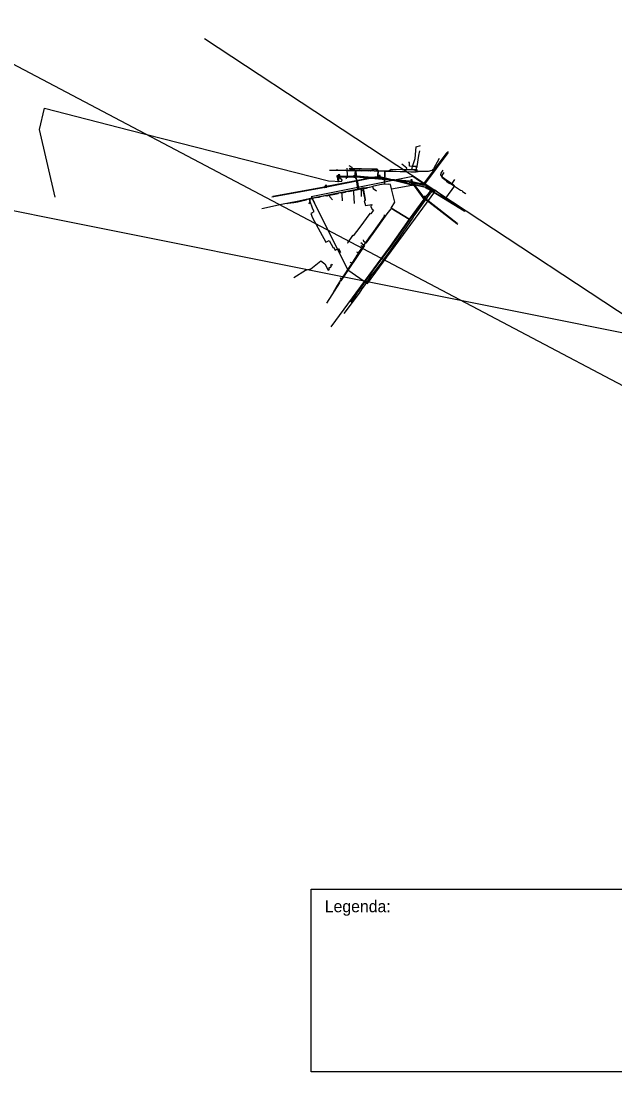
# Model space of a CAD drawing. Extents: x -748299 to -739481, y -1044416 to -1042142.
# Drawn here: x -742397 to -741644, y -1044416 to -1043083 of the extents above; entities that cross this region are included whole.
import ezdxf

# ---------------------------------------------------------------- set-up
doc = ezdxf.new("R2010")
doc.units = 0
for name, color, linetype in [('Vrstva 1', 7, 'Continuous'), ('Vrstva 2', 7, 'Continuous'), ('Vrstva 3', 7, 'Continuous'), ('Vrstva 5', 7, 'Continuous'), ('Vrstva 63', 7, 'Continuous')]:
    doc.layers.add(name, color=color, linetype=linetype)

msp = doc.modelspace()

# ---------------------------------------------------------------- linework, layer by layer
at = {"layer": 'Vrstva 1'}
for points in [[(-741897, -1043257.6), (-741895.6, -1043243), (-741890.1, -1043241)], [(-742005.4, -1043272.4), (-741996.1, -1043272.5), (-741983.4, -1043272.8)], [(-741997.2, -1043272.1), (-741994.8, -1043272.2), (-741991.4, -1043272.3), (-741985.3, -1043272.4), (-741984.3, -1043272), (-741983.3, -1043272.4), (-741978.9, -1043272.5)], [(-741983.4, -1043272.8), (-741975, -1043273), (-741964.6, -1043273.2), (-741951.8, -1043273)], [(-741980.6, -1043270), (-741978.3, -1043271.6)], [(-741978.9, -1043272.5), (-741977.2, -1043272.5)], [(-741978.3, -1043270.1), (-741967.9, -1043270.3), (-741965.1, -1043270.4), (-741946, -1043270.8), (-741945.6, -1043271.3)], [(-741978.3, -1043271.6), (-741973.5, -1043271.7), (-741971.5, -1043272), (-741968, -1043272.2), (-741967.1, -1043272.5), (-741955.2, -1043272.5), (-741945.6, -1043271.3)], [(-741977.2, -1043272.5), (-741972.7, -1043272.4)], [(-741973.2, -1043280.5), (-741973, -1043277.5), (-741972.7, -1043272.4)], [(-741972.7, -1043272.4), (-741973, -1043277.5), (-741973.2, -1043280.5), (-741971.9, -1043283.2), (-741970.8, -1043285.7)], [(-741972.7, -1043272.4), (-741971.7, -1043272.4), (-741967.7, -1043272.7), (-741960.5, -1043272.9), (-741956.3, -1043273.2), (-741954.9, -1043272.6), (-741953.4, -1043273.1), (-741946.8, -1043272.9), (-741945.2, -1043272.6), (-741943.5, -1043273.1), (-741934.5, -1043273.2), (-741929.4, -1043272.9), (-741921.1, -1043273.7), (-741909.8, -1043274), (-741908.9, -1043273.2), (-741907.3, -1043269.8), (-741913.8, -1043264.8)], [(-741967.7, -1043272.7), (-741971.7, -1043272.4)], [(-741967.9, -1043270.3), (-741965.1, -1043270.4)], [(-741951.8, -1043273), (-741948.8, -1043273.1)], [(-741948.8, -1043273.1), (-741944, -1043273.4)], [(-741945.6, -1043271.3), (-741944.6, -1043271.2)], [(-741945.6, -1043271.3), (-741944, -1043273.1)], [(-741944, -1043273.1), (-741944.6, -1043271.2)], [(-741944, -1043273.4), (-741944.1, -1043279.7), (-741944.3, -1043280.2)], [(-741944.1, -1043279.7), (-741944, -1043273.4)], [(-741944, -1043273.1), (-741944, -1043273.4)], [(-741944, -1043273.1), (-741943.7, -1043273.4)], [(-741944, -1043273.4), (-741943.7, -1043273.4)], [(-741943.7, -1043273.4), (-741935.2, -1043273.6)], [(-741935.2, -1043273.6), (-741935.8, -1043289.8)], [(-741935.2, -1043273.6), (-741931, -1043273.7)], [(-741931, -1043273.7), (-741927.2, -1043271.2), (-741913.2, -1043271.5), (-741906.2, -1043271.6), (-741901.3, -1043271.7)], [(-741931, -1043273.7), (-741916.1, -1043274), (-741902.2, -1043274.5), (-741898.2, -1043274.6), (-741895, -1043274.6), (-741895.1, -1043273.9)], [(-741902.2, -1043274.5), (-741898.2, -1043274.6)], [(-741895.2, -1043271.7), (-741895.1, -1043271)], [(-741895.2, -1043273), (-741895.2, -1043271.7)], [(-741895.1, -1043273.9), (-741895.2, -1043273)], [(-741895.1, -1043270.6), (-741895.1, -1043270)], [(-741895.1, -1043271), (-741895.1, -1043270.6)], [(-741861.7, -1043272.3), (-741864.2, -1043276.3), (-741864.6, -1043278.2), (-741862.6, -1043281.9), (-741857.6, -1043285.6), (-741857.2, -1043286.4), (-741854.5, -1043288.3), (-741853, -1043289.4), (-741850.7, -1043290)], [(-741970.8, -1043285.7), (-741971.9, -1043283.2), (-741973.2, -1043280.5)], [(-741970.8, -1043285.7), (-741971.1, -1043287.2), (-741969.8, -1043296.3), (-741969.1, -1043296.8)], [(-741970.8, -1043285.7), (-741971.1, -1043287.2)], [(-741971.1, -1043287.2), (-741969.8, -1043296.3)], [(-741970.8, -1043285.7), (-741970.6, -1043287.2), (-741969.2, -1043296.1), (-741969.1, -1043296.8)], [(-741970.8, -1043285.7), (-741970.2, -1043287.1), (-741968.7, -1043295.9), (-741969.1, -1043296.8)], [(-741970.8, -1043285.7), (-741970.6, -1043287.2)], [(-741970.2, -1043287.1), (-741970.8, -1043285.7)], [(-741970.6, -1043287.2), (-741969.2, -1043296.1)], [(-741968.7, -1043295.9), (-741970.2, -1043287.1)], [(-741859.8, -1043283), (-741849.6, -1043289.7)], [(-741857.6, -1043285.6), (-741857.2, -1043286.4), (-741854.5, -1043288.3)], [(-741846.9, -1043284.3), (-741848.8, -1043286.9), (-741850.7, -1043290)], [(-741848.8, -1043286.9), (-741850.7, -1043290)], [(-742031.1, -1043308.4), (-742011.4, -1043304.6), (-742001, -1043302.6), (-741979.3, -1043298.2), (-741965.1, -1043295.3)], [(-742005.8, -1043304.2), (-742000.7, -1043303.3), (-741994.6, -1043302.1), (-741993.6, -1043301.2), (-741991.3, -1043300.8), (-741989.8, -1043301)], [(-741989.8, -1043301), (-741985.7, -1043300.2), (-741983.2, -1043299.1), (-741981.3, -1043299.3), (-741969.1, -1043296.8)], [(-741985.7, -1043300.2), (-741989.8, -1043301)], [(-741989, -1043311.3), (-741989.4, -1043303.2), (-741989.8, -1043301)], [(-741969.1, -1043296.8), (-741965.6, -1043296.2)], [(-741965.6, -1043296.2), (-741964.7, -1043295.9), (-741961.1, -1043295.2), (-741958.8, -1043295.2), (-741956.7, -1043294.3), (-741951, -1043293.2), (-741950.3, -1043295.5)], [(-741965.6, -1043296.2), (-741965.1, -1043298.7)], [(-741961.1, -1043295.2), (-741964.7, -1043295.9)], [(-741961.8, -1043294.9), (-741955.4, -1043293.8)], [(-741955.4, -1043293.8), (-741951.4, -1043293)], [(-741951.4, -1043293), (-741949.1, -1043292.5)], [(-741950.3, -1043295.5), (-741946, -1043298.7)], [(-741949.1, -1043292.5), (-741939.7, -1043290.4)], [(-741939.7, -1043290.4), (-741938.9, -1043290.2)], [(-741927, -1043296.1), (-741928.3, -1043290.7), (-741930.6, -1043290.4)], [(-741927, -1043296.1), (-741901, -1043291.5), (-741899, -1043291.2)], [(-741927, -1043296.1), (-741901, -1043291.5)], [(-741878.3, -1043299.5), (-741881.5, -1043304)], [(-741875.9, -1043298.7), (-741878.3, -1043299.5)], [(-741847.1, -1043292.4), (-741858.4, -1043307.9)], [(-741850.7, -1043290), (-741839.5, -1043298), (-741837.8, -1043298.1), (-741837.2, -1043298.5), (-741836.8, -1043299.6), (-741833.5, -1043301.8), (-741832.6, -1043302.5)], [(-741849.6, -1043289.7), (-741847.1, -1043292.4)], [(-742091.1, -1043321.1), (-742066.5, -1043315.7), (-742046.3, -1043311.8), (-742031.1, -1043308.4)], [(-742059.2, -1043314.6), (-742057.9, -1043314.3), (-742054.5, -1043313.9), (-742050.7, -1043313.5), (-742045.5, -1043312.4), (-742042.1, -1043311.6), (-742034.9, -1043310.1), (-742033.4, -1043309.4), (-742030.4, -1043309)], [(-742045.5, -1043312.4), (-742042.1, -1043311.6)], [(-742030.4, -1043309), (-742029.2, -1043308.8), (-742028.8, -1043308.8)], [(-742028.8, -1043308.8), (-742027.2, -1043308.4)], [(-742016.6, -1043306.3), (-742018.2, -1043306.6), (-742021.5, -1043307.2), (-742027.2, -1043308.4)], [(-742027.2, -1043308.4), (-742026.7, -1043310.5)], [(-742026.7, -1043310.5), (-742024.6, -1043313.7)], [(-742021.5, -1043307.2), (-742018.2, -1043306.6)], [(-742005.8, -1043304.2), (-742008.7, -1043305.4), (-742010.9, -1043305.2), (-742016.6, -1043306.3)], [(-742001.5, -1043310.2), (-742005.2, -1043306.4), (-742005.8, -1043304.2)], [(-741841.5, -1043319.7), (-741865.5, -1043305.2)], [(-741936.8, -1043329.1), (-741935.4, -1043330.1)], [(-741927.3, -1043320.8), (-741904.3, -1043334.4)], [(-741899.3, -1043332.2), (-741897, -1043328.7)], [(-741935.4, -1043330.1), (-741951.7, -1043353.1), (-741953.5, -1043355.5), (-741963.6, -1043369.7)], [(-741899.3, -1043332.2), (-741908.8, -1043345.5), (-741926.1, -1043370.6), (-741933.2, -1043380.7)], [(-741951.7, -1043353.1), (-741953.5, -1043355.5)], [(-741964, -1043366), (-741961.2, -1043368), (-741991.2, -1043412.9), (-741992.7, -1043413.8), (-741992.8, -1043415.5), (-742009.3, -1043441.2)], [(-741927.8, -1043369.4), (-741949.6, -1043398.5), (-741971.4, -1043429.2), (-741973.5, -1043432.5)], [(-741963.6, -1043369.7), (-741965.6, -1043368.3)], [(-741970.2, -1043379.4), (-741970.8, -1043380.3), (-741972.6, -1043383.1), (-741977.3, -1043390.3)], [(-741970.8, -1043380.3), (-741972.6, -1043383.1)], [(-741969, -1043377.4), (-741970.8, -1043376.3)], [(-741969, -1043377.4), (-741970.2, -1043379.4)], [(-741963.6, -1043369.7), (-741969, -1043377.4)], [(-741933.2, -1043380.7), (-741936, -1043384.4)], [(-741977.3, -1043390.3), (-741990.1, -1043410.1)], [(-741977.3, -1043390.3), (-741978.9, -1043389.4)], [(-741938.8, -1043388.1), (-741947.7, -1043399.8), (-741951.4, -1043404.2)], [(-741936, -1043384.4), (-741938.8, -1043388.1)], [(-741991.4, -1043409.3), (-741990.1, -1043410.1)], [(-741953.2, -1043406.5), (-741956.8, -1043412.6)], [(-741951.4, -1043404.2), (-741953.2, -1043406.5)], [(-741990.6, -1043410.8), (-741995.7, -1043418.7), (-741997.4, -1043421.6), (-742000.5, -1043426.7)], [(-741995.7, -1043418.7), (-741997.4, -1043421.6)], [(-741990.1, -1043410.1), (-741990.6, -1043410.8)], [(-741961.7, -1043419.2), (-741964.4, -1043422.8)], [(-741960.8, -1043417.9), (-741961.7, -1043419.2)], [(-741958.2, -1043414.5), (-741960.8, -1043417.9)], [(-741956.8, -1043412.6), (-741958.2, -1043414.5)], [(-741967.9, -1043428.5), (-741987.2, -1043454.2)], [(-741973.5, -1043432.5), (-741978.9, -1043439.7)], [(-741964.4, -1043422.8), (-741967.9, -1043428.5)]]:
    msp.add_lwpolyline(points, dxfattribs=at)
msp.add_lwpolyline([(-742028.7, -1044184.3), (-740808.7, -1044184.3), (-740808.7, -1044416.3), (-742028.7, -1044416.3)], close=True, dxfattribs=at)
at = {"layer": 'Vrstva 2'}
for points in [[(-742353.5, -1043306.5), (-742373, -1043220.8), (-742367, -1043194), (-742258.5, -1043221.6), (-742006.7, -1043285.8), (-741990.4, -1043286.8), (-741989.5, -1043284.6), (-741992.7, -1043282.5), (-741994.5, -1043282.4), (-741994.5, -1043280.3)], [(-741855.1, -1043248.9), (-741885.4, -1043290), (-741886.5, -1043291.1), (-741902.5, -1043286.9), (-741973.2, -1043280.5)], [(-741895.1, -1043270), (-741894.3, -1043267.8), (-741892.3, -1043253.9), (-741891, -1043248.1)], [(-741900.1, -1043267.6), (-741904.1, -1043267.4), (-741904.1, -1043262.7), (-741905.3, -1043262.7)], [(-741900.1, -1043267.6), (-741897, -1043257.6)], [(-741866.5, -1043257.5), (-741873.7, -1043270.7), (-741875.8, -1043272.7), (-741880.2, -1043274.1), (-741893, -1043274.2)], [(-741983.4, -1043272.8), (-741982.8, -1043281.7), (-741984.7, -1043282.5), (-741984.3, -1043283.4)], [(-741983.6, -1043270), (-741983.4, -1043272.8)], [(-741981, -1043266.6), (-741977.2, -1043268.5), (-741977.2, -1043272.5)], [(-741978.3, -1043271.6), (-741978.3, -1043270.1)], [(-741935.8, -1043289.8), (-741935.2, -1043273.6)], [(-741901.3, -1043271.7), (-741900.1, -1043267.6)], [(-741901.3, -1043271.7), (-741899.7, -1043271.7)], [(-741895.1, -1043270), (-741895.8, -1043267.8), (-741900.1, -1043267.6)], [(-741899.7, -1043271.7), (-741895.2, -1043271.7)], [(-741895.1, -1043273.9), (-741899.7, -1043271.7)], [(-741895.2, -1043271.7), (-741894.6, -1043271.7), (-741894.3, -1043274.2)], [(-741895.1, -1043273.9), (-741894.3, -1043274.2)], [(-741894.3, -1043274.2), (-741893, -1043274.2)], [(-741860.5, -1043275.5), (-741863.1, -1043279.1), (-741862.8, -1043280.8), (-741859.8, -1043283)], [(-742078.7, -1043306.3), (-742010.8, -1043293.8), (-741945.3, -1043281), (-741943.3, -1043281.1)], [(-741973.2, -1043280.5), (-741994.5, -1043280.3)], [(-741944.3, -1043280.2), (-741943.3, -1043281.1)], [(-741943.3, -1043281.1), (-741941.7, -1043281), (-741900.5, -1043291.1), (-741899, -1043291.2)], [(-741974, -1043314.7), (-741974.5, -1043300.6), (-741975, -1043297.8), (-741963.5, -1043295.9), (-741960.6, -1043309.6), (-741960.4, -1043311)], [(-741964.8, -1043305.9), (-741965.1, -1043298.7), (-741965.6, -1043296.2)], [(-741963, -1043295.1), (-741965.1, -1043295.3)], [(-741961.8, -1043294.9), (-741963, -1043295.1)], [(-741963, -1043295.1), (-741960.2, -1043309.6), (-741960.4, -1043311)], [(-741938.9, -1043290.2), (-741935.8, -1043289.8)], [(-741935.8, -1043289.8), (-741930.6, -1043290.4)], [(-741904.3, -1043334.4), (-741927.3, -1043320.8), (-741922.7, -1043313), (-741927, -1043296.1)], [(-741899, -1043291.2), (-741897.9, -1043291.9), (-741886.6, -1043307), (-741885.6, -1043307.8)], [(-741833.3, -1043324.9), (-741882.7, -1043294.7), (-741884, -1043294), (-741897.4, -1043291.2), (-741899, -1043291.2)], [(-741880, -1043305.1), (-741877.1, -1043301.2)], [(-741865.5, -1043305.2), (-741872.7, -1043300.6), (-741875.4, -1043300), (-741877.1, -1043301.2)], [(-741858.4, -1043307.9), (-741872, -1043298), (-741875.9, -1043298.7)], [(-741847.1, -1043292.4), (-741858.4, -1043307.9)], [(-742031.2, -1043315.3), (-742030, -1043311.2), (-742030.4, -1043309)], [(-742027.8, -1043327), (-742028.1, -1043326.4), (-742025.1, -1043324.8), (-742026.6, -1043321.8), (-742030.6, -1043311.1), (-742031.1, -1043308.4)], [(-741960.4, -1043311), (-741961.4, -1043311.2), (-741960, -1043317.4), (-741952, -1043316), (-741951.9, -1043316.8), (-741953, -1043317.8), (-741953, -1043319), (-741951.5, -1043321.7), (-741949.6, -1043323), (-741952.3, -1043326.6)], [(-741885.7, -1043309.6), (-741903.8, -1043334.7), (-741927.8, -1043369.4)], [(-741886.1, -1043309.3), (-741904.3, -1043334.4)], [(-741897, -1043328.7), (-741884.1, -1043310.8)], [(-741885.6, -1043307.8), (-741886.5, -1043309), (-741886.1, -1043309.3)], [(-741886.1, -1043309.3), (-741885.7, -1043309.6)], [(-741885.7, -1043309.6), (-741884.1, -1043310.8)], [(-741885.6, -1043307.8), (-741884.7, -1043306.6), (-741883.9, -1043307.2)], [(-741885.6, -1043307.8), (-741884.4, -1043308.7), (-741842.8, -1043340.9)], [(-741884.1, -1043310.8), (-741882.3, -1043308.3)], [(-741883.9, -1043307.2), (-741881.5, -1043304)], [(-741882.3, -1043308.3), (-741883.9, -1043307.2)], [(-741882.3, -1043308.3), (-741880, -1043305.1)], [(-741881.5, -1043304), (-741880, -1043305.1)], [(-741858.4, -1043307.9), (-741847.4, -1043315.6)], [(-742027.8, -1043327), (-742029.1, -1043327.5), (-742027.1, -1043332.7), (-742010, -1043363.8), (-742005.8, -1043361.8), (-742000.9, -1043370.8), (-742000.3, -1043370.5), (-741998.5, -1043373.8), (-741994.2, -1043371.6), (-741991.6, -1043376.4), (-741992.2, -1043376.7)], [(-741952.3, -1043326.6), (-741953.2, -1043328), (-741954.4, -1043327.3), (-741967.1, -1043344.8)], [(-741932.7, -1043328), (-741950.4, -1043352.8), (-741959.3, -1043364.9), (-741961.9, -1043363.1)], [(-741927.7, -1043321.3), (-741932.7, -1043328)], [(-741904.3, -1043334.4), (-741928.6, -1043368.8), (-742003.8, -1043471)], [(-741967.1, -1043344.8), (-741975.3, -1043355.8), (-741976.5, -1043355.3), (-741982.5, -1043364.6), (-741982.2, -1043364.7)], [(-741967.1, -1043344.8), (-741966.7, -1043345.1)], [(-741964, -1043366), (-741965.9, -1043364.6)], [(-741961.9, -1043363.1), (-741962.3, -1043360.8)], [(-742050.8, -1043408.4), (-742035.8, -1043399.1), (-742029.1, -1043397.5), (-742016.6, -1043387.6), (-742011.5, -1043391.4), (-742007.3, -1043399.2), (-742005.3, -1043398.3), (-742006.2, -1043397.7), (-742004.9, -1043395.3), (-742004.1, -1043396.1), (-742002.8, -1043394.2), (-742003.9, -1043393.3)], [(-742003.9, -1043393.3), (-742002.9, -1043391.7), (-742002.4, -1043392.1)], [(-742002.4, -1043392.1), (-742001.5, -1043392.7)], [(-741978.9, -1043389.4), (-741979.3, -1043389.2)], [(-741991.4, -1043409.3), (-741991.8, -1043409.1)]]:
    msp.add_lwpolyline(points, dxfattribs=at)
at = {"layer": 'Vrstva 3'}
for points in [[(-741885.7, -1043289.7), (-741856.4, -1043250.2)], [(-741855.6, -1043250.6), (-741885.1, -1043290.2)], [(-741972, -1043279.4), (-741972.5, -1043273.7)], [(-741972.1, -1043273.7), (-741971.7, -1043279.4)], [(-741954.3, -1043282.5), (-742009.3, -1043293.3)], [(-741952.6, -1043282.7), (-742009.2, -1043293.8)], [(-741992.8, -1043279.6), (-741996.2, -1043279.6), (-741996.2, -1043281.1)], [(-741996.2, -1043281.1), (-741995.5, -1043281.6)], [(-741995.5, -1043281.6), (-741995.4, -1043284.8)], [(-741995.4, -1043284.8), (-741995.1, -1043284.8)], [(-741995.1, -1043284.8), (-741995, -1043286.8)], [(-741995, -1043286.8), (-741994.1, -1043286.8)], [(-741993.9, -1043284.8), (-741994.1, -1043286.8)], [(-741993.6, -1043284.8), (-741993.9, -1043284.8)], [(-741993.6, -1043281.7), (-741992.8, -1043281.1)], [(-741993.6, -1043284.8), (-741993.6, -1043281.7)], [(-741992.8, -1043279.9), (-741992.8, -1043279.6)], [(-741992.8, -1043279.9), (-741974.9, -1043280)], [(-741992.8, -1043280.8), (-741974.9, -1043280.7)], [(-741992.8, -1043281.1), (-741992.8, -1043280.8)], [(-741972, -1043279.4), (-741975, -1043279.5)], [(-741975, -1043279.5), (-741974.9, -1043280)], [(-741974.8, -1043281.4), (-741974.9, -1043280.7)], [(-741974.8, -1043281.4), (-741971.3, -1043281.3)], [(-741971.4, -1043279.4), (-741971.7, -1043279.4)], [(-741971.4, -1043279.4), (-741971.4, -1043280.1)], [(-741951.4, -1043281.9), (-741971.4, -1043280.1)], [(-741971.3, -1043281.3), (-741971.3, -1043280.9)], [(-741971.3, -1043280.9), (-741954.3, -1043282.5)], [(-741951.4, -1043281.9), (-741954.3, -1043282.5)], [(-741954.3, -1043282.5), (-741952.6, -1043282.7)], [(-741949.7, -1043282.1), (-741952.6, -1043282.7)], [(-741952.6, -1043282.7), (-741925.3, -1043285.2)], [(-741945.2, -1043280.7), (-741951.4, -1043281.9)], [(-741949.7, -1043282.1), (-741951.4, -1043281.9)], [(-741945.2, -1043281.2), (-741949.7, -1043282.1)], [(-741931.2, -1043283.8), (-741949.7, -1043282.1)], [(-741945.2, -1043280.7), (-741944.3, -1043280.2)], [(-741945.2, -1043281.2), (-741944.3, -1043281.6)], [(-741944.3, -1043280.2), (-741942.2, -1043280.2)], [(-741944.3, -1043281.8), (-741944.3, -1043281.6)], [(-741942.2, -1043281.8), (-741944.3, -1043281.8)], [(-741942.2, -1043280.2), (-741942.2, -1043280.5)], [(-741941.7, -1043280.8), (-741942.2, -1043280.5)], [(-741941.7, -1043281.3), (-741942.2, -1043281.5)], [(-741942.2, -1043281.5), (-741942.2, -1043281.8)], [(-741927.7, -1043284.1), (-741941.7, -1043280.8)], [(-741931.2, -1043283.8), (-741941.7, -1043281.3)], [(-741927.7, -1043284.1), (-741931.2, -1043283.8)], [(-741925.3, -1043285.2), (-741931.2, -1043283.8)], [(-741921.8, -1043285.6), (-741927.7, -1043284.1)], [(-741904.2, -1043286.3), (-741927.7, -1043284.1)], [(-741900.7, -1043291.4), (-741925.3, -1043285.2)], [(-741925.3, -1043285.2), (-741921.8, -1043285.6)], [(-741900.4, -1043290.8), (-741921.8, -1043285.6)], [(-741921.8, -1043285.6), (-741904.3, -1043287.2)], [(-741904.4, -1043287.7), (-741904.3, -1043287.2)], [(-741904.4, -1043287.7), (-741901.8, -1043288.1)], [(-741904.1, -1043285.8), (-741904.2, -1043286.3)], [(-741904.1, -1043285.8), (-741900.7, -1043286.4)], [(-741901.8, -1043288.1), (-741900.4, -1043290.8)], [(-741901.1, -1043288.2), (-741900.9, -1043288.3)], [(-741901.1, -1043288.2), (-741900.2, -1043290.2)], [(-741900.9, -1043287.9), (-741889.5, -1043290.7)], [(-741900.9, -1043288.3), (-741900.9, -1043287.9)], [(-741900.7, -1043286.4), (-741900.8, -1043287.1)], [(-741889.3, -1043289.9), (-741900.8, -1043287.1)], [(-741889.1, -1043289.4), (-741889.3, -1043289.9)], [(-741889.1, -1043289.4), (-741886.7, -1043289.8)], [(-741886.7, -1043289.8), (-741886, -1043289.3)], [(-741886, -1043289.3), (-741885.7, -1043289.7)], [(-742012.4, -1043293.9), (-742077.2, -1043305.8)], [(-742012.3, -1043294.4), (-742077.1, -1043306.3)], [(-742012.4, -1043293.9), (-742011.9, -1043293.7)], [(-742012.3, -1043294.4), (-742011.8, -1043294.4)], [(-742012, -1043293.2), (-742009.9, -1043292.9)], [(-742011.9, -1043293.7), (-742012, -1043293.2)], [(-742011.8, -1043294.4), (-742011.7, -1043294.8)], [(-742009.6, -1043294.4), (-742011.7, -1043294.8)], [(-742009.9, -1043292.9), (-742009.8, -1043293.3)], [(-742009.3, -1043293.3), (-742009.8, -1043293.3)], [(-742009.2, -1043293.8), (-742009.7, -1043294)], [(-742009.6, -1043294.4), (-742009.7, -1043294)], [(-741900.3, -1043291.6), (-741900.7, -1043291.4)], [(-741900.3, -1043291.6), (-741900.3, -1043292)], [(-741898.2, -1043292.1), (-741900.3, -1043292)], [(-741900.2, -1043290.2), (-741897.7, -1043290.3)], [(-741898.2, -1043292.1), (-741897.9, -1043292.4)], [(-741886.9, -1043307.4), (-741897.9, -1043292.4)], [(-741897.7, -1043290.3), (-741897.7, -1043290.7)], [(-741897.7, -1043290.7), (-741897.4, -1043290.9)], [(-741897.7, -1043291.6), (-741897.4, -1043291.5)], [(-741897.7, -1043291.6), (-741897.5, -1043291.9)], [(-741897.5, -1043291.9), (-741886.3, -1043306.6)], [(-741897.4, -1043290.9), (-741883.9, -1043293.8)], [(-741884.1, -1043294.2), (-741897.4, -1043291.5)], [(-741889.6, -1043291.2), (-741889.5, -1043290.7)], [(-741886.1, -1043292), (-741889.6, -1043291.2)], [(-741884.7, -1043290.6), (-741886.1, -1043292)], [(-741884.7, -1043290.6), (-741885.1, -1043290.2)], [(-741883.9, -1043294.6), (-741884.1, -1043294.2)], [(-741883.9, -1043294.6), (-741884, -1043294.9)], [(-741882.2, -1043295.9), (-741884, -1043294.9)], [(-741883.9, -1043293.8), (-741883.4, -1043293.8)], [(-741883.3, -1043293.5), (-741883.4, -1043293.8)], [(-741883.3, -1043293.5), (-741881.4, -1043294.5)], [(-741882, -1043295.6), (-741882.2, -1043295.9)], [(-741882, -1043295.6), (-741881.5, -1043295.6)], [(-741881.4, -1043294.5), (-741881.6, -1043294.8)], [(-741881.3, -1043295.2), (-741881.6, -1043294.8)], [(-741834.7, -1043324.4), (-741881.5, -1043295.6)], [(-741881.3, -1043295.2), (-741834.5, -1043324)], [(-741887.2, -1043307.8), (-741886.9, -1043307.4)], [(-741885.2, -1043309.3), (-741887.2, -1043307.8)], [(-741886, -1043306.2), (-741886.3, -1043306.6)], [(-741886, -1043306.2), (-741884, -1043307.7)], [(-741885.2, -1043309.3), (-741884.9, -1043308.9)], [(-741844.1, -1043340.5), (-741884.9, -1043308.9)], [(-741884, -1043307.7), (-741884.3, -1043308.1)], [(-741884.3, -1043308.1), (-741843.5, -1043339.7)]]:
    msp.add_lwpolyline(points, dxfattribs=at)
for points in [[(-741994.5, -1043280.3), (-741992.5, -1043280.3), (-741992.5, -1043278.3), (-741994.5, -1043278.3)], [(-741973.2, -1043280.5), (-741971.2, -1043280.5), (-741971.2, -1043278.5), (-741973.2, -1043278.5)], [(-741943.3, -1043281.1), (-741941.3, -1043281.1), (-741941.3, -1043279.1), (-741943.3, -1043279.1)], [(-741902.5, -1043286.9), (-741900.5, -1043286.9), (-741900.5, -1043284.9), (-741902.5, -1043284.9)], [(-741899, -1043291.2), (-741897, -1043291.2), (-741897, -1043289.2), (-741899, -1043289.2)], [(-741886.5, -1043291.1), (-741884.5, -1043291.1), (-741884.5, -1043289.1), (-741886.5, -1043289.1)], [(-742010.8, -1043293.8), (-742008.8, -1043293.8), (-742008.8, -1043291.8), (-742010.8, -1043291.8)], [(-741882.7, -1043294.7), (-741880.7, -1043294.7), (-741880.7, -1043292.7), (-741882.7, -1043292.7)], [(-741885.6, -1043307.8), (-741883.6, -1043307.8), (-741883.6, -1043305.8), (-741885.6, -1043305.8)]]:
    msp.add_lwpolyline(points, close=True, dxfattribs=at)
at = {"layer": 'Vrstva 5'}
for points in [[(-748298.8, -1042142.2), (-739481, -1043910.1)], [(-740942, -1043911), (-742164, -1043106)], [(-740942, -1043911), (-742439, -1043121)]]:
    msp.add_lwpolyline(points, dxfattribs=at)
at = {"layer": 'Vrstva 63'}
msp.add_lwpolyline([(-741899.9, -1043280.6), (-742028.7, -1043306.2), (-741982.2, -1043398.7), (-741957.2, -1043416.3), (-741872.1, -1043299.8), (-741899.9, -1043280.6)], close=True, dxfattribs=at)

# ---------------------------------------------------------------- texts
at = {"layer": 'Vrstva 1'}
msp.add_text('Legenda:', height=15, dxfattribs=at).set_placement((-742011.5, -1044213.7))

doc.saveas('drawing.dxf')
